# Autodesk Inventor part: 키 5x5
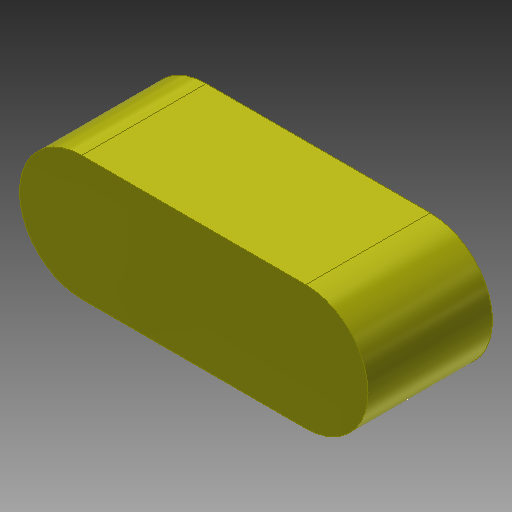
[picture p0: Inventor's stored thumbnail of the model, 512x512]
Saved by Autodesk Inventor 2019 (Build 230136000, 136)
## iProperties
Created: 2014-10
Part Number: 키 5x5
Document SubType Name: Modeling
Designer: KYOUNG IL JANG
Density: 7.86 g/cm^3
Mass: 2.54015 g
Surface Area: 2.9781 cm^2
Volume: 0.323175 cm^3
Material: 강철, 연강
Appearance: 노란색
Author: SeoGD™ [www.esajin.kr]
Revision Number: 1
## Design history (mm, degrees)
sketch "스케치1"
  geometry: L1 (-4.5, -2.5)-(4.5, -2.5); L2 (4.5, 2.5)-(-4.5, 2.5); A1 r 2.5 centre (4.5, 0) between (4.5, -2.5) and (4.5, 2.5); A2 r 2.5 centre (-4.5, 0) between (-4.5, 2.5) and (-4.5, -2.5); 2 further points
  constraints: 4 end point, 4 point on circle, 4 tangent, 2 centre point, 1 horizontal, 1 horizontal alignment, 1 midpoint, 1 parallel, 1 vertical alignment
  dimensions: "d0" = 5 distance between parallel lines of L1 L2; "d1" = 14 dimension on A1 A2
extrude "돌출1" new body sketch "스케치1" stored distance "d2" = 5; taper "d3" = 0 deg
node "솔리드1"
